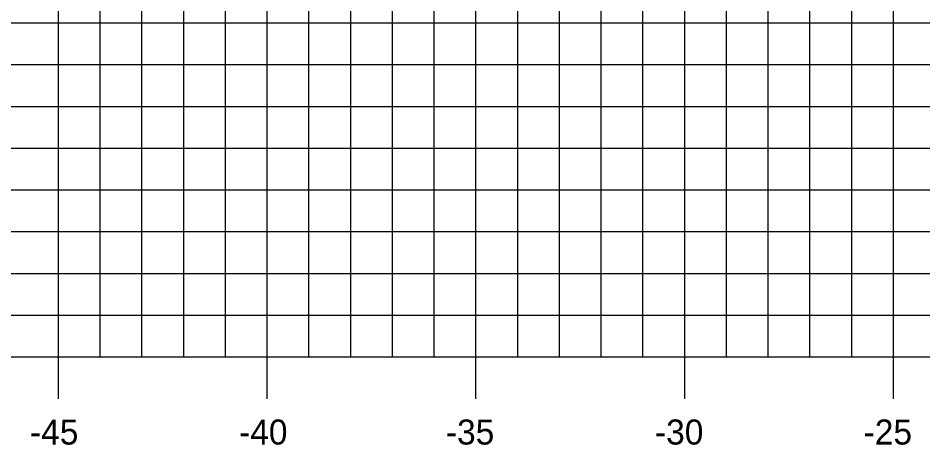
# Model space of a CAD drawing. Extents: x 1146525 to 1146695, y 608981 to 609091.
# Drawn here: x 1146561.7 to 1146583.38, y 609018.23 to 609028.45 of the extents above; entities that cross this region are included whole.
import ezdxf

# ---------------------------------------------------------------- set-up
doc = ezdxf.new("R2010")
doc.units = 0
for name, color, linetype in [('H_V ANNOTATION', 7, 'Continuous'), ('MAJOR', 7, 'Continuous'), ('MINOR', 7, 'Continuous')]:
    doc.layers.add(name, color=color, linetype=linetype)

msp = doc.modelspace()

# ---------------------------------------------------------------- linework, layer by layer
at = {"layer": 'MAJOR'}
for p, q in [((1146562.671, 609020.335), (1146562.671, 609045.335)), ((1146567.671, 609020.335), (1146567.671, 609045.335)), ((1146572.671, 609020.335), (1146572.671, 609045.335)), ((1146577.671, 609020.335), (1146577.671, 609045.335)), ((1146582.671, 609020.335), (1146582.671, 609045.335)), ((1146537.671, 609025.335), (1146677.671, 609025.335)), ((1146537.671, 609020.335), (1146677.671, 609020.335)), ((1146537.671, 609020.335), (1146677.671, 609020.335)), ((1146562.671, 609019.333), (1146562.671, 609020.335)), ((1146567.671, 609019.333), (1146567.671, 609020.335)), ((1146572.671, 609019.333), (1146572.671, 609020.335)), ((1146577.671, 609019.333), (1146577.671, 609020.335)), ((1146582.671, 609019.333), (1146582.671, 609020.335))]:
    msp.add_line(p, q, dxfattribs=at)
at = {"layer": 'MINOR'}
for p, q in [((1146563.671, 609020.335), (1146563.671, 609045.335)), ((1146564.671, 609020.335), (1146564.671, 609045.335)), ((1146565.671, 609020.335), (1146565.671, 609045.335)), ((1146566.671, 609020.335), (1146566.671, 609045.335)), ((1146568.671, 609020.335), (1146568.671, 609045.335)), ((1146569.671, 609020.335), (1146569.671, 609045.335)), ((1146570.671, 609020.335), (1146570.671, 609045.335)), ((1146571.671, 609020.335), (1146571.671, 609045.335)), ((1146573.671, 609020.335), (1146573.671, 609045.335)), ((1146574.671, 609020.335), (1146574.671, 609045.335)), ((1146575.671, 609020.335), (1146575.671, 609045.335)), ((1146576.671, 609020.335), (1146576.671, 609045.335)), ((1146578.671, 609020.335), (1146578.671, 609045.335)), ((1146579.671, 609020.335), (1146579.671, 609045.335)), ((1146580.671, 609020.335), (1146580.671, 609045.335)), ((1146581.671, 609020.335), (1146581.671, 609045.335)), ((1146537.671, 609028.335), (1146677.671, 609028.335)), ((1146537.671, 609027.335), (1146677.671, 609027.335)), ((1146537.671, 609026.335), (1146677.671, 609026.335)), ((1146537.671, 609024.335), (1146677.671, 609024.335)), ((1146537.671, 609023.335), (1146677.671, 609023.335)), ((1146537.671, 609022.335), (1146677.671, 609022.335)), ((1146537.671, 609021.335), (1146677.671, 609021.335))]:
    msp.add_line(p, q, dxfattribs=at)

# ---------------------------------------------------------------- texts
at = {"layer": 'H_V ANNOTATION'}
for s, p in [('-45', (1146561.989, 609018.235)), ('-40', (1146566.997, 609018.235)), ('-35', (1146571.951, 609018.235)), ('-30', (1146576.959, 609018.235)), ('-25', (1146581.957, 609018.235))]:
    msp.add_text(s, height=0.6, dxfattribs=at).set_placement(p)

doc.saveas('drawing.dxf')
